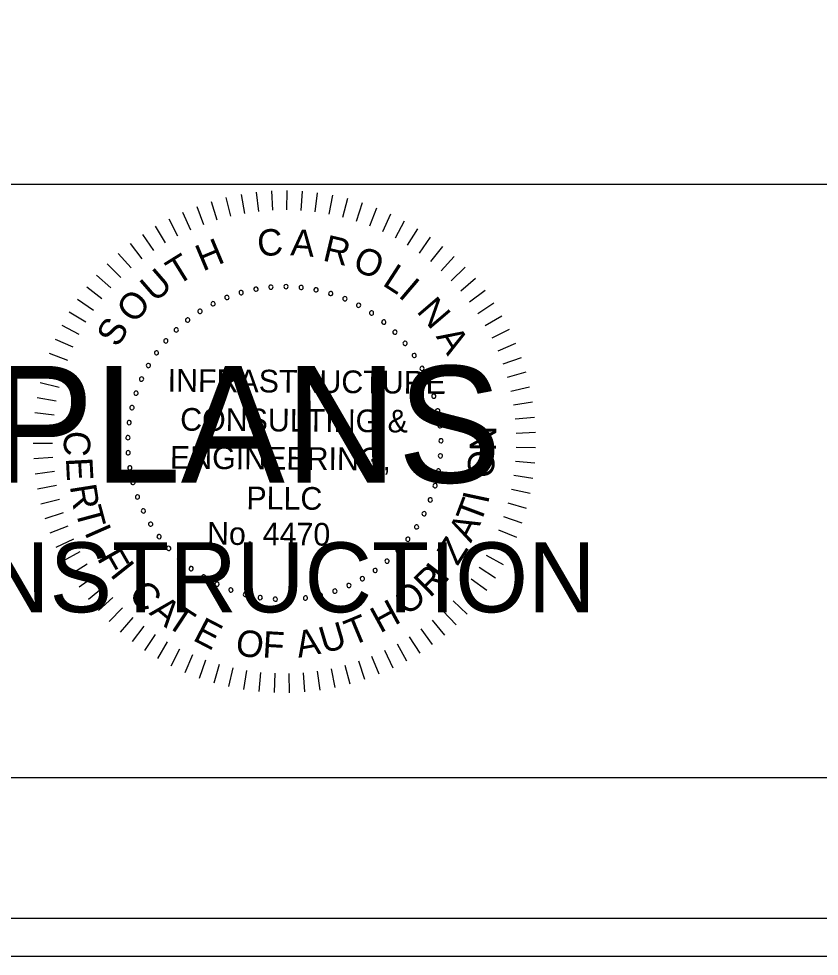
# Model space of a CAD drawing. Extents: x 967 to 1746, y 964 to 7904.
# Drawn here: x 1189.3 to 1212.88, y 4603.72 to 4631.36 of the extents above; entities that cross this region are included whole.
import ezdxf

# ---------------------------------------------------------------- set-up
doc = ezdxf.new("R2010")
doc.units = 0
for name, color, linetype in [('RD_SHT_Bndy', 7, 'Continuous'), ('RD_SHT_IplotShp', 7, 'Continuous'), ('RD_SHT_Misc1', 7, 'Continuous'), ('RD_SHT_Misc2', 7, 'Continuous'), ('RD_Sketch1', 7, 'Continuous')]:
    doc.layers.add(name, color=color, linetype=linetype)

msp = doc.modelspace()

# ---------------------------------------------------------------- linework, layer by layer
at = {"layer": 'RD_SHT_Bndy'}
for p, q in [((996.114, 4626.486), (1323.886, 4626.486)), ((1323.886, 4608.983), (996.114, 4608.983))]:
    msp.add_line(p, q, dxfattribs=at)
at = {"layer": 'RD_SHT_IplotShp'}
for points in [[(967.409, 4603.72), (1326.285, 4603.72), (1326.285, 4823.72), (967.409, 4823.72)], [(988.525, 4604.84), (1326.285, 4604.84), (1326.285, 4822.6), (988.525, 4822.6)]]:
    msp.add_lwpolyline(points, close=True, dxfattribs=at)
at = {"layer": 'RD_SHT_Misc1'}
for p, q in [((1195.403, 4626.09), (1195.536, 4625.536)), ((1195.846, 4626.181), (1195.945, 4625.62)), ((1196.292, 4626.245), (1196.357, 4625.68)), ((1196.742, 4626.282), (1196.772, 4625.714)), ((1197.194, 4626.292), (1197.189, 4625.723)), ((1197.645, 4626.274), (1197.606, 4625.706)), ((1198.094, 4626.228), (1198.02, 4625.664)), ((1198.54, 4626.156), (1198.432, 4625.596)), ((1194.54, 4625.827), (1194.739, 4625.293)), ((1194.968, 4625.971), (1195.134, 4625.427)), ((1198.98, 4626.056), (1198.838, 4625.504)), ((1199.414, 4625.929), (1199.238, 4625.387)), ((1194.122, 4625.656), (1194.353, 4625.136)), ((1199.839, 4625.777), (1199.63, 4625.246)), ((1200.253, 4625.598), (1200.013, 4625.082)), ((1193.321, 4625.241), (1193.614, 4624.752)), ((1193.715, 4625.461), (1193.978, 4624.956)), ((1200.656, 4625.395), (1200.385, 4624.894)), ((1192.94, 4624.997), (1193.263, 4624.528)), ((1201.047, 4625.167), (1200.745, 4624.684)), ((1192.576, 4624.731), (1192.926, 4624.282)), ((1201.422, 4624.917), (1201.092, 4624.453)), ((1192.228, 4624.443), (1192.605, 4624.016)), ((1201.781, 4624.643), (1201.424, 4624.2)), ((1191.899, 4624.134), (1192.301, 4623.731)), ((1202.124, 4624.349), (1201.739, 4623.928)), ((1202.447, 4624.034), (1202.038, 4623.638)), ((1191.589, 4623.805), (1192.015, 4623.428)), ((1202.751, 4623.7), (1202.318, 4623.329)), ((1191.299, 4623.459), (1191.748, 4623.108)), ((1203.034, 4623.348), (1202.579, 4623.004)), ((1191.032, 4623.095), (1191.501, 4622.772)), ((1203.294, 4622.979), (1202.82, 4622.664)), ((1190.787, 4622.716), (1191.274, 4622.422)), ((1203.532, 4622.595), (1203.04, 4622.31)), ((1190.565, 4622.323), (1191.07, 4622.059)), ((1203.746, 4622.198), (1203.237, 4621.943)), ((1190.368, 4621.916), (1190.888, 4621.684)), ((1203.936, 4621.788), (1203.412, 4621.564)), ((1190.196, 4621.499), (1190.729, 4621.299)), ((1204.1, 4621.367), (1203.563, 4621.176)), ((1190.05, 4621.072), (1190.594, 4620.905)), ((1204.238, 4620.937), (1203.691, 4620.779)), ((1189.93, 4620.636), (1190.484, 4620.503)), ((1204.349, 4620.5), (1203.794, 4620.375)), ((1189.837, 4620.195), (1190.398, 4620.095)), ((1204.434, 4620.056), (1203.872, 4619.966)), ((1189.771, 4619.748), (1190.337, 4619.683)), ((1204.491, 4619.608), (1203.925, 4619.552)), ((1189.732, 4619.298), (1190.301, 4619.267)), ((1204.522, 4619.158), (1203.953, 4619.137)), ((1189.721, 4618.847), (1190.29, 4618.851)), ((1204.524, 4618.706), (1203.955, 4618.72)), ((1189.737, 4618.396), (1190.306, 4618.434)), ((1204.499, 4618.256), (1203.932, 4618.304)), ((1189.781, 4617.946), (1190.346, 4618.019)), ((1204.447, 4617.807), (1203.884, 4617.89)), ((1189.852, 4617.5), (1190.412, 4617.608)), ((1204.367, 4617.363), (1203.81, 4617.479)), ((1189.951, 4617.06), (1190.502, 4617.201)), ((1204.261, 4616.924), (1203.712, 4617.074)), ((1190.076, 4616.626), (1190.617, 4616.8)), ((1204.128, 4616.492), (1203.589, 4616.676)), ((1190.227, 4616.2), (1190.757, 4616.408)), ((1203.969, 4616.07), (1203.442, 4616.286)), ((1190.403, 4615.785), (1190.92, 4616.024)), ((1203.784, 4615.658), (1203.271, 4615.906)), ((1190.605, 4615.381), (1191.106, 4615.651)), ((1190.831, 4614.99), (1191.315, 4615.291)), ((1203.574, 4615.258), (1203.078, 4615.537)), ((1203.341, 4614.871), (1202.862, 4615.18)), ((1191.081, 4614.614), (1191.545, 4614.943)), ((1203.085, 4614.5), (1202.626, 4614.837)), ((1191.353, 4614.253), (1191.796, 4614.61)), ((1202.806, 4614.145), (1202.368, 4614.509)), ((1191.646, 4613.91), (1192.067, 4614.293)), ((1202.506, 4613.807), (1202.092, 4614.197)), ((1191.96, 4613.585), (1192.356, 4613.994)), ((1192.293, 4613.28), (1192.664, 4613.712)), ((1202.186, 4613.488), (1201.796, 4613.903)), ((1192.644, 4612.996), (1192.988, 4613.45)), ((1201.491, 4612.912), (1201.155, 4613.372)), ((1201.847, 4613.19), (1201.484, 4613.628)), ((1193.011, 4612.734), (1193.327, 4613.208)), ((1201.119, 4612.657), (1200.811, 4613.136)), ((1193.394, 4612.495), (1193.68, 4612.987)), ((1200.731, 4612.425), (1200.453, 4612.922)), ((1193.791, 4612.279), (1194.047, 4612.788)), ((1194.2, 4612.088), (1194.424, 4612.612)), ((1199.918, 4612.034), (1199.702, 4612.561)), ((1200.331, 4612.217), (1200.083, 4612.73)), ((1194.62, 4611.923), (1194.812, 4612.459)), ((1195.05, 4611.783), (1195.208, 4612.33)), ((1199.063, 4611.745), (1198.913, 4612.295)), ((1199.495, 4611.877), (1199.312, 4612.416)), ((1195.487, 4611.67), (1195.612, 4612.225)), ((1195.93, 4611.584), (1196.021, 4612.146)), ((1196.377, 4611.524), (1196.434, 4612.091)), ((1196.828, 4611.493), (1196.85, 4612.062)), ((1197.279, 4611.488), (1197.267, 4612.058)), ((1197.73, 4611.512), (1197.683, 4612.079)), ((1198.179, 4611.562), (1198.097, 4612.126)), ((1198.624, 4611.64), (1198.508, 4612.198))]:
    msp.add_line(p, q, dxfattribs=at)
for centre, start, end in [((1195.851, 4623.285), 16.1422, 196.1422), ((1195.851, 4623.285), 196.1422, 16.1422), ((1196.285, 4623.388), 10.6038, 190.6038), ((1196.285, 4623.388), 190.6038, 10.6038), ((1196.727, 4623.447), 5.0653, 185.0653), ((1196.727, 4623.447), 185.0653, 5.0653), ((1197.172, 4623.464), 359.5268, 179.5268), ((1197.172, 4623.464), 179.5268, 359.5268), ((1197.617, 4623.438), 173.9884, 353.9884), ((1197.617, 4623.438), 353.9884, 173.9884), ((1198.057, 4623.369), 168.4499, 348.4499), ((1198.057, 4623.369), 348.4499, 168.4499), ((1198.489, 4623.258), 342.9114, 162.9114), ((1195.429, 4623.142), 21.6807, 201.6807), ((1195.429, 4623.142), 201.6807, 21.6807), ((1198.489, 4623.258), 162.9114, 342.9114), ((1198.908, 4623.106), 157.373, 337.373), ((1198.908, 4623.106), 337.373, 157.373), ((1194.637, 4622.736), 32.7576, 212.7576), ((1194.637, 4622.736), 212.7576, 32.7576), ((1195.023, 4622.958), 27.2191, 207.2191), ((1195.023, 4622.958), 207.2191, 27.2191), ((1199.31, 4622.914), 151.8345, 331.8345), ((1199.31, 4622.914), 331.8345, 151.8345), ((1194.274, 4622.478), 38.2961, 218.2961), ((1194.274, 4622.478), 218.2961, 38.2961), ((1199.692, 4622.684), 146.2961, 326.2961), ((1199.692, 4622.684), 326.2961, 146.2961), ((1200.05, 4622.419), 320.7576, 140.7576), ((1193.937, 4622.186), 43.8345, 223.8345), ((1193.937, 4622.186), 223.8345, 43.8345), ((1200.05, 4622.419), 140.7576, 320.7576), ((1193.63, 4621.862), 49.373, 229.373), ((1200.38, 4622.12), 135.2191, 315.2191), ((1200.38, 4622.12), 315.2191, 135.2191), ((1193.63, 4621.862), 229.373, 49.373), ((1200.68, 4621.79), 129.6807, 309.6807), ((1200.68, 4621.79), 309.6807, 129.6807), ((1193.356, 4621.511), 54.9114, 234.9114), ((1193.356, 4621.511), 234.9114, 54.9114), ((1200.947, 4621.433), 124.1422, 304.1422), ((1200.947, 4621.433), 304.1422, 124.1422), ((1193.117, 4621.135), 60.4499, 240.4499), ((1193.117, 4621.135), 240.4499, 60.4499), ((1201.179, 4621.052), 118.6038, 298.6038), ((1201.179, 4621.052), 298.6038, 118.6038), ((1192.915, 4620.737), 65.9884, 245.9884), ((1192.915, 4620.737), 245.9884, 65.9884), ((1201.372, 4620.651), 113.0653, 293.0653), ((1201.372, 4620.651), 293.0653, 113.0653), ((1192.753, 4620.322), 71.5268, 251.5268), ((1192.753, 4620.322), 251.5268, 71.5268), ((1201.526, 4620.233), 107.5268, 287.5268), ((1201.526, 4620.233), 287.5268, 107.5268), ((1192.632, 4619.894), 77.0653, 257.0653), ((1192.632, 4619.894), 257.0653, 77.0653), ((1201.638, 4619.801), 101.9884, 281.9884), ((1201.638, 4619.801), 281.9884, 101.9884), ((1192.552, 4619.455), 82.6038, 262.6038), ((1192.552, 4619.455), 262.6038, 82.6038), ((1201.709, 4619.361), 96.4499, 276.4499), ((1201.709, 4619.361), 276.4499, 96.4499), ((1192.515, 4619.011), 88.1422, 268.1422), ((1192.515, 4619.011), 268.1422, 88.1422), ((1201.737, 4618.917), 90.9114, 270.9114), ((1201.737, 4618.917), 270.9114, 90.9114), ((1192.522, 4618.565), 93.6807, 273.6807), ((1192.522, 4618.565), 273.6807, 93.6807), ((1201.721, 4618.471), 85.373, 265.373), ((1201.721, 4618.471), 265.373, 85.373), ((1192.571, 4618.122), 99.2191, 279.2191), ((1192.571, 4618.122), 279.2191, 99.2191), ((1201.663, 4618.029), 79.8345, 259.8345), ((1201.663, 4618.029), 259.8345, 79.8345), ((1192.662, 4617.686), 104.7576, 284.7576), ((1192.662, 4617.686), 284.7576, 104.7576), ((1201.563, 4617.595), 74.2961, 254.2961), ((1201.563, 4617.595), 254.2961, 74.2961), ((1192.796, 4617.261), 110.2961, 290.2961), ((1192.796, 4617.261), 290.2961, 110.2961), ((1201.42, 4617.173), 68.7576, 248.7576), ((1201.42, 4617.173), 248.7576, 68.7576), ((1192.97, 4616.851), 115.8345, 295.8345), ((1192.97, 4616.851), 295.8345, 115.8345), ((1201.238, 4616.766), 63.2191, 243.2191), ((1201.238, 4616.766), 243.2191, 63.2191), ((1193.182, 4616.459), 121.373, 301.373), ((1193.182, 4616.459), 301.373, 121.373), ((1201.018, 4616.379), 57.6807, 237.6807), ((1201.018, 4616.379), 237.6807, 57.6807), ((1193.432, 4616.09), 126.9114, 306.9114), ((1193.432, 4616.09), 306.9114, 126.9114), ((1200.761, 4616.014), 52.1422, 232.1422), ((1200.761, 4616.014), 232.1422, 52.1422), ((1193.715, 4615.746), 132.4499, 312.4499), ((1193.715, 4615.746), 312.4499, 132.4499), ((1200.47, 4615.677), 46.6038, 226.6038), ((1200.47, 4615.677), 226.6038, 46.6038), ((1194.031, 4615.431), 137.9884, 317.9884), ((1194.031, 4615.431), 317.9884, 137.9884), ((1200.148, 4615.369), 41.0653, 221.0653), ((1200.148, 4615.369), 221.0653, 41.0653), ((1194.376, 4615.149), 143.5268, 323.5268), ((1194.376, 4615.149), 323.5268, 143.5268), ((1199.798, 4615.093), 35.5268, 215.5268), ((1199.798, 4615.093), 215.5268, 35.5268), ((1194.746, 4614.901), 149.0653, 329.0653), ((1194.746, 4614.901), 329.0653, 149.0653), ((1195.139, 4614.69), 334.6038, 154.6038), ((1199.422, 4614.853), 29.9884, 209.9884), ((1199.422, 4614.853), 209.9884, 29.9884), ((1195.139, 4614.69), 154.6038, 334.6038), ((1195.55, 4614.517), 160.1422, 340.1422), ((1195.55, 4614.517), 340.1422, 160.1422), ((1198.611, 4614.486), 18.9114, 198.9114), ((1198.611, 4614.486), 198.9114, 18.9114), ((1199.026, 4614.65), 24.4499, 204.4499), ((1199.026, 4614.65), 204.4499, 24.4499), ((1195.975, 4614.386), 165.6807, 345.6807), ((1195.975, 4614.386), 345.6807, 165.6807), ((1196.412, 4614.295), 171.2191, 351.2191), ((1196.412, 4614.295), 351.2191, 171.2191), ((1196.855, 4614.248), 356.7576, 176.7576), ((1196.855, 4614.248), 176.7576, 356.7576), ((1197.301, 4614.243), 2.2961, 182.2961), ((1197.301, 4614.243), 182.2961, 2.2961), ((1197.745, 4614.282), 7.8345, 187.8345), ((1197.745, 4614.282), 187.8345, 7.8345), ((1198.183, 4614.363), 13.373, 193.373), ((1198.183, 4614.363), 193.373, 13.373)]:
    msp.add_arc(centre, 0.0627, start, end, dxfattribs=at)
at = {"layer": 'RD_Sketch1'}
msp.add_lwpolyline([(967.409, 4603.72), (1326.285, 4603.72), (1326.285, 4823.72), (967.409, 4823.72)], close=True, dxfattribs=at)

# ---------------------------------------------------------------- texts
at = {"layer": 'RD_SHT_Misc1'}
for s, height, rotation, p in [('C', 0.78, 4.7281, (1196.355, 4624.346)), ('A', 0.78, 355.6981, (1197.29, 4624.39)), ('R', 0.78, 346.6681, (1198.222, 4624.238)), ('H', 0.78, 22.7882, (1194.72, 4623.904)), ('T', 0.78, 31.8182, (1193.961, 4623.478)), ('O', 0.78, 337.638, (1199.096, 4623.972)), ('U', 0.78, 40.8482, (1193.306, 4622.976)), ('L', 0.78, 327.108, (1199.981, 4623.52)), ('I', 0.78, 319.578, (1200.451, 4623.182)), ('O', 0.78, 49.8782, (1192.707, 4622.341)), ('N', 0.78, 310.548, (1200.994, 4622.728)), ('S', 0.78, 58.9083, (1192.211, 4621.642)), ('A', 0.78, 301.5179, (1201.576, 4621.991)), ('INFRASTRUCTURE', 0.66873, 359.5268, (1193.682, 4620.367)), ('CONSULTING &', 0.66873, 359.5268, (1194.051, 4619.217)), ('C', 0.78, 267.025, (1190.646, 4619.227)), ('N', 0.78, 89.2085, (1203.359, 4618.604)), ('ENGINEERING,', 0.66873, 359.5268, (1193.751, 4618.095)), ('E', 0.78, 273.025, (1190.685, 4618.408)), ('O', 0.78, 83.2085, (1203.26, 4617.786)), ('R', 0.78, 279.025, (1190.799, 4617.583)), ('PLLC', 0.6687, 359.5268, (1196.002, 4616.9)), ('T', 0.78, 69.3954, (1202.891, 4616.428)), ('I', 0.78, 77.9093, (1203.121, 4617.032)), ('T', 0.78, 285.025, (1190.955, 4616.878)), ('I', 0.78, 293.7713, (1191.221, 4616.225)), ('No. 4470', 0.6687, 359.5268, (1194.843, 4615.855)), ('A', 0.78, 63.3954, (1202.616, 4615.888)), ('Z', 0.78, 57.3954, (1202.224, 4615.206)), ('F', 0.78, 299.7713, (1191.589, 4615.455)), ('I', 0.78, 308.5268, (1191.965, 4614.973)), ('I', 0.78, 52.3339, (1201.856, 4614.69)), ('R', 0.78, 44.5268, (1201.415, 4614.267)), ('C', 0.78, 314.5268, (1192.496, 4614.346)), ('O', 0.78, 38.5268, (1200.73, 4613.731)), ('A', 0.78, 320.5268, (1193.115, 4613.822)), ('H', 0.78, 28.5268, (1199.942, 4613.23)), ('T', 0.78, 326.5268, (1193.602, 4613.478)), ('E', 0.78, 332.5268, (1194.394, 4613.051)), ('T', 0.78, 22.5268, (1199.108, 4612.856)), ('O', 0.78, 350.5268, (1195.647, 4612.614)), ('A', 0.78, 10.5268, (1197.537, 4612.517)), ('U', 0.78, 16.5268, (1198.288, 4612.638)), ('F', 0.78, 356.5268, (1196.465, 4612.532))]:
    msp.add_text(s, height=height, rotation=rotation, dxfattribs=at).set_placement(p)
at = {"layer": 'RD_SHT_Misc2'}
for s, height, p in [('FINAL PLANS', 3.4375, (1174.145, 4617.685)), ('NOT FOR CONSTRUCTION', 2.0625, (1170.901, 4613.86))]:
    msp.add_text(s, height=height, dxfattribs=at).set_placement(p)

doc.saveas('drawing.dxf')
